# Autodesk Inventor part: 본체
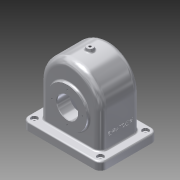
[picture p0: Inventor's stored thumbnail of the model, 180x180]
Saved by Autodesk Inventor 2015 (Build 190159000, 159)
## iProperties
Created: 2016-10
Part Number: 본체
Material: 알루미늄 6061
Document SubType Name: Modeling
Designer: LineLG02
Density: 2.7 g/cm^3
Appearance: 알루미늄 - 평지
Mass: 1160.93 g
Surface Area: 1199.61 cm^2
Volume: 429.975 cm^3
Author: LineLG02
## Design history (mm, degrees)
sketch "스케치1"
  geometry: L1 (-63, -55)-(63, -55); L2 (75, -43)-(75, 43); L3 (63, 55)-(-63, 55); L4 (-75, 43)-(-75, -43); C1 r 2.5 at (63, 43); C2 r 2.5 at (63, -43); C3 r 2.5 at (-63, -43); C4 r 2.5 at (-63, 43); A1 r 12 centre (63, 43) between (75, 43) and (63, 55); A2 r 12 centre (63, -43) between (63, -55) and (75, -43); A3 r 12 centre (-63, -43) between (-75, -43) and (-63, -55); A4 r 12 centre (-63, 43) between (-63, 55) and (-75, 43); 4 further points
  constraints: 8 centre point, 8 end point, 8 point on circle, 8 tangent, 6 equal radius, 6 point on line, 4 coincident, 2 parallel, 1 horizontal, 1 perpendicular
  dimensions: "d0" = 150 distance of point (-75, 55) point (75, 55); "d1" = 110 distance of point (75, 55) point (75, -55); "d2" = 12 radius of A1; "d3" = 5 diameter of C1
extrude "돌출1" new body sketch "스케치1" distance "d4" = 15; taper "d5" = 0 deg
sketch "스케치2"
  geometry: L1 (-75, -43)-(-75, 43) reference; L2 (-63, 55)-(63, 55) reference; L3 (75, 43)-(75, -43) reference; L4 (63, -55)-(-63, -55) reference; C1 r 2.5 at (63, -43) reference; C2 r 2.5 at (63, 43) reference; C3 r 2.5 at (-63, 43) reference; C4 r 2.5 at (-63, -43) reference; C5 r 2.5 at (-63, -43) reference; C6 r 6 at (-63, -43); C7 r 6 at (-63, 43); C8 r 6 at (63, 43); C9 r 6 at (63, -43); A1 r 12 centre (-63, -43) between (-75, -43) and (-63, -55) reference; A2 r 12 centre (-63, 43) between (-63, 55) and (-75, 43) reference; A3 r 12 centre (63, 43) between (75, 43) and (63, 55) reference; A4 r 12 centre (63, -43) between (63, -55) and (75, -43) reference; 1 further point
  constraints: 4 centre point, 4 coincident, 3 equal radius
  dimensions: "d6" = 12 diameter of C6
extrude "돌출2" cut sketch "스케치2" distance "d7" = 5; taper "d8" = 0 deg
node "작업 평면1"
sketch "스케치8"
  geometry: L1 (58, -38.5)-(-58, -38.5); L2 (-58, -38.5)-(-58, 38.5); L3 (-58, 38.5)-(58, 38.5); L4 (58, 38.5)-(58, -38.5); L5 (58, -38.5)-(-58, 38.5); L6 (-58, -38.5)-(58, 38.5); 1 further point
  constraints: 12 end point, 2 midpoint, 2 parallel, 1 horizontal, 1 perpendicular
  dimensions: "d28" = 116 distance of L2.end L3.end; "d29" = 77 distance of L1.end L2.end
extrude "돌출5" join sketch "스케치8" stored distance "d30" = 5; taper "d31" = 0 deg
sketch "스케치9"
  geometry: L1 (-58, 38.5)-(58, 38.5) reference; L2 (58, 38.5)-(58, -38.5) reference; L3 (58, -38.5)-(-58, -38.5) reference; L4 (-58, -38.5)-(-58, 38.5) reference; L5 (-58, -38.5)-(0, -38.5); L6 (0, -38.5)-(0, 38.5); L7 (0, 38.5)-(-58, 38.5); L8 (-58, 38.5)-(-58, -38.5); 1 further point
  constraints: 8 end point, 2 parallel, 1 horizontal, 1 midpoint, 1 perpendicular
revolve "회전4" sketch "스케치9" stored, may be unused: angle "d32" = 90 deg
sketch "스케치10"
  geometry: L1 (-52, 80)-(-52, 0); L2 (52, 80)-(52, 0); L3 (-52, 0)-(52, 0); A1 r 52 centre (0, 80) between (52, 80) and (-52, 80); 2 further points
  constraints: 6 end point, 2 point on circle, 2 vertical, 1 centre point, 1 coincident, 1 perpendicular
  dimensions: "d34" = 52 radius of A1
extrude "돌출6" cut sketch "스케치10" stored distance "d35" = 67; taper "d36" = 0 deg
sketch "스케치11"
  geometry: L1 (138, 38.5)-(138, -38.5) reference; L2 (138, -38.5)-(15, -38.5) reference; L3 (15, -38.5)-(15, -55) reference; L4 (15, -55)-(0, -55) reference; L5 (0, -55)-(0, -33.5) reference; L6 (0, -33.5)-(132, -33.5) reference; L7 (132, -33.5)-(132, 33.5) reference; L8 (132, 33.5)-(0, 33.5) reference; L9 (0, 33.5)-(0, 55) reference; L10 (0, 55)-(15, 55) reference; L11 (15, 55)-(15, 38.5) reference; L12 (15, 38.5)-(138, 38.5) reference; L13 (102.5, 43.5)-(102.5, 38.5); L14 (104.747, 33.5)-(93, 19.5); L15 (93, 19.5)-(85, 19.5); L16 (65, 19.5)-(65, 43.5); L17 (102.5, 43.5)-(86, 43.5); L18 (102.5, 38.5)-(104.747, 33.5); L19 (85, 42.5)-(85, 19.5); L20 (85, 42.5)-(86, 43.5); 3 further points
  constraints: 16 end point, 7 point on line, 2 perpendicular, 2 vertical, 1 horizontal
  dimensions: "d37" = 65 distance from line of L9 L16.start; "d38" = 75 diameter of L13 L16; "d39" = 56 diameter of L14.end L16; "d40" = 50 deg angle of L15 L14; "d41" = 5 distance of L13.start L13.end; "d42" = 24 distance of L16.start L16.end; "d43" = 40 diameter of L19 L16; "d44" = 1 distance of L19.start point (85, 43.5); "d45" = 1 distance of L17.end point (85, 43.5) (= d44)
revolve "회전5" sketch "스케치11" stored, may be unused: angle "d46" = 90 deg
sketch "스케치12"
  geometry: C1 r 20 at (0, 0); 1 further point
  constraints: 1 centre point
  dimensions: "d47" = 40 diameter of C1
extrude "돌출7" cut sketch "스케치12" stored distance "d48" = 67; taper "d49" = 0 deg
sketch "스케치13"
  geometry: L1 (-5, -15)-(121, -15) reference; L2 (-5, 50)-(121, 50); C1 r 31 at (58, 50); 1 further point
  constraints: 2 end point, 1 centre point, 1 midpoint, 1 parallel
  dimensions: "d50" = 65 distance between parallel lines of L1 L2; "d51" = 62 diameter of C1
extrude "돌출8" join sketch "스케치13" distance "d52" = 10; taper "d53" = 0 deg
sketch "스케치14"
  geometry: L1 (65.398, -55)-(65.398, -50) reference; L2 (65.398, -50)-(73.665, -50) reference; L3 (73.665, -50)-(73.665, -65) reference; L4 (73.665, -65)-(-73.665, -65) reference; L5 (-73.665, -65)-(-73.665, -50) reference; L6 (-73.665, -50)-(-65.398, -50) reference; L7 (-65.398, -50)-(-65.398, -55) reference; L8 (-65.398, -55)-(-60.602, -55) reference; L9 (-60.602, -55)-(-60.602, -50) reference; L10 (-60.602, -50)-(60.602, -50) reference; L11 (60.602, -50)-(60.602, -55) reference; L12 (60.602, -55)-(65.398, -55) reference; C1 r 31 at (0, 0) reference; C2 r 20 at (0, 0); 1 further point
  constraints: 1 centre point, 1 coincident
  dimensions: "d54" = 40 diameter of C2
extrude "돌출9" cut sketch "스케치14" stored distance "d55" = 10; taper "d56" = 0 deg
sketch "스케치15"
  geometry: L1 (65.398, -55)-(65.398, -50) reference; L2 (65.398, -50)-(73.665, -50) reference; L3 (73.665, -50)-(73.665, -65) reference; L4 (73.665, -65)-(-73.665, -65) reference; L5 (-73.665, -65)-(-73.665, -50) reference; L6 (-73.665, -50)-(-65.398, -50) reference; L7 (-65.398, -50)-(-65.398, -55) reference; L8 (-65.398, -55)-(-60.602, -55) reference; L9 (-60.602, -55)-(-60.602, -50) reference; L10 (-60.602, -50)-(60.602, -50) reference; L11 (60.602, -50)-(60.602, -55) reference; L12 (60.602, -55)-(65.398, -55) reference; C1 r 20 at (0, 0) reference; C2 r 31 at (0, 0) reference; A1 r 26 centre (0, 0) between (0, 26) and (26, 0); 3 further points
  constraints: 4 point on circle, 1 centre point, 1 coincident
  dimensions: "d57" = 52 diameter of A1
hole "구멍1" sketch "스케치15" at (0, 26), (26, 0), (0, -26), (-26, 0) diameter "d58" = 2.459; stored, may be unused: countersink angle "d62" = 90 deg, drill point angle "d64" = 118 deg; dims "d59" = 6, "d60" = 4, "d61" = 2, "d63" = 8
sketch "스케치16"
  geometry: L1 (-68.979, -50)-(-68.979, -55) reference; L2 (-68.979, -55)-(-65.449, -55) reference; L3 (-65.449, -55)-(-65.449, -65) reference; L4 (-65.449, -65)-(-74.99, -65) reference; L5 (-74.99, -65)-(-74.99, -50) reference; L6 (-74.99, -50)-(-68.979, -50) reference; L7 (57.021, -50)-(57.021, -55) reference; L8 (57.021, -55)-(60.551, -55) reference; L9 (60.551, -55)-(60.551, -65) reference; L10 (60.551, -65)-(-60.551, -65) reference; L11 (-60.551, -65)-(-60.551, -55) reference; L12 (-60.551, -55)-(-57.021, -55) reference; L13 (-57.021, -55)-(-57.021, -50) reference; L14 (-57.021, -50)-(57.021, -50) reference; L15 (68.979, -55)-(68.979, -50) reference; L16 (68.979, -50)-(74.99, -50) reference; L17 (74.99, -50)-(74.99, -65) reference; L18 (74.99, -65)-(65.449, -65) reference; L19 (65.449, -65)-(65.449, -55) reference; L20 (65.449, -55)-(68.979, -55) reference; C1 r 37.5 at (0, 0) reference; C2 r 21 at (0, 0) reference; A1 r 29 centre (0, 0) between (0, 29) and (29, 0); 3 further points
  constraints: 4 point on circle, 1 centre point, 1 coincident
  dimensions: "d65" = 58 diameter of A1
hole "구멍2" sketch "스케치16" at (0, 29), (29, 0), (0, -29), (-29, 0) diameter "d66" = 2.459; stored, may be unused: countersink angle "d70" = 90 deg, drill point angle "d72" = 118 deg; dims "d67" = 6, "d68" = 4, "d69" = 2, "d71" = 8
sketch "스케치17"
  geometry: L1 (138, 38.5)-(138, -38.5) reference; L2 (132, 33.5)-(80, 33.5) reference; L3 (0, 33.5)-(0, -33.5); L4 (144, 6)-(144, -6); L5 (144, 6)-(134.405, 7.692); L6 (144, -6)-(134.405, -7.692); L7 (134.405, 7.692)-(134.405, -7.692); L8 (144, 0)-(134.405, 0); 1 further point
  constraints: 12 end point, 2 midpoint, 2 vertical, 1 parallel
  dimensions: "d75" = 144 distance between parallel lines of L3 L4; "d78" = 100 deg angle of L5 L1; "d79" = 12 distance of L4.start L4.end
revolve "회전6" sketch "스케치17" stored, may be unused: angle "d80" = 90 deg
sketch "스케치18"
  geometry: 2 further points
  constraints: 1 coincident
hole "구멍3" sketch "스케치18" at (0, 0) diameter "d81" = 4.459; stored, may be unused: countersink angle "d85" = 90 deg, drill point angle "d87" = 118 deg; dims "d82" = 10, "d83" = 4, "d84" = 2, "d86" = 12.8
sketch "스케치19"
  geometry: L1 (0, 65)-(0, 0) reference; 2 further points
  constraints: 1 other
  dimensions: "d88" = 38.5 distance from line of point (38.5, 25) L1; "d89" = 40 distance of point (38.5, -15) point (38.5, 25)
feature "엠보싱1" sketch "스케치19" dims "d1" = 110, "d90" = 0.5, "d91" = 0
fillet "모깎기1" dims "d92" = 13, "d93" = 8
fillet "모깎기2" dims "d94" = 3
chamfer "모따기1" distance "d95" = 1; stored, may be unused: second distance "d96" = 2, angle "d97" = 45 deg
node "솔리드1"
node "절단 모서리 투영1"
node "절단 모서리 투영5"
node "절단 모서리 투영6"
node "절단 모서리 투영7"
node "절단 모서리 투영8"
node "절단 모서리 투영9"
